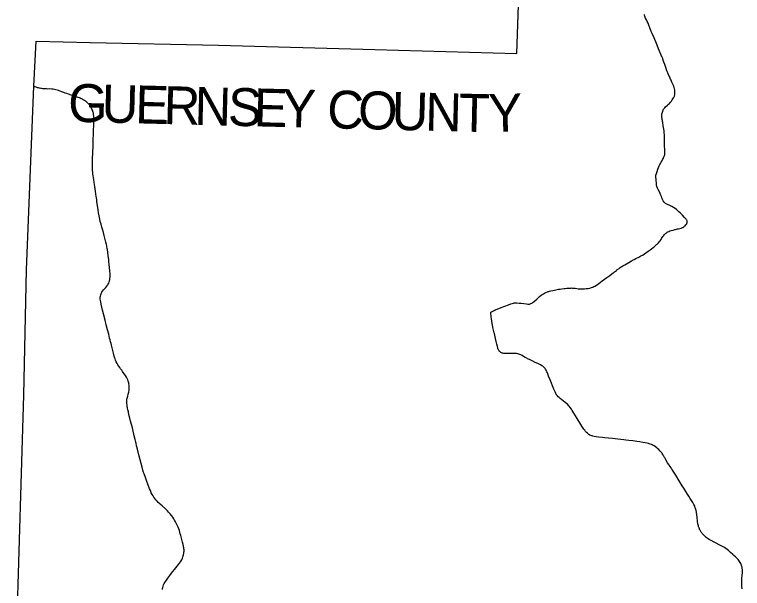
# Model space of a CAD drawing. Extents: x 1913970 to 2397567, y 78841 to 829347.
# Drawn here: x 2186978 to 2206160, y 770418 to 785537 of the extents above; entities that cross this region are included whole.
import ezdxf

# ---------------------------------------------------------------- set-up
doc = ezdxf.new("R2010")
doc.units = 0
for name, color, linetype in [('GM_X_County', 7, 'Continuous'), ('GM_X_County_Text', 7, 'Continuous'), ('GM_X_State_Location', 7, 'Continuous'), ('GM_X_State_Route', 7, 'Continuous')]:
    doc.layers.add(name, color=color, linetype=linetype)

msp = doc.modelspace()

# ---------------------------------------------------------------- linework, layer by layer
at = {"layer": 'GM_X_County'}
msp.add_lwpolyline([(2186978, 767293), (2187218, 775508), (2187296, 778812), (2187489, 783655), (2187543, 784833), (2188969, 784801), (2192356, 784732), (2196471, 784613), (2200213, 784515), (2200352, 788594), (2200607, 796487), (2200640, 798126), (2200752, 800346), (2200989, 806420)], dxfattribs=at)
at = {"layer": 'GM_X_State_Route'}
for points in [[(2204051, 784396), (2204046, 784409), (2204022, 784470), (2203977, 784572), (2203950, 784635), (2203911, 784733), (2203876, 784818), (2203831, 784920), (2203780, 785037), (2203757, 785095), (2203721, 785186), (2203693, 785262), (2203671, 785313), (2203652, 785354), (2203630, 785399), (2203606, 785445), (2203600, 785455), (2203596, 785464), (2203592, 785474), (2203588, 785483), (2203585, 785493), (2203584, 785499), (2203581, 785509), (2203579, 785522), (2203578, 785530), (2203577, 785542)], [(2204202, 783166), (2204210, 783173), (2204236, 783198), (2204262, 783228), (2204286, 783258), (2204310, 783288), (2204329, 783314), (2204343, 783339), (2204354, 783359), (2204361, 783374), (2204367, 783391), (2204370, 783405), (2204374, 783421), (2204378, 783447), (2204380, 783477), (2204379, 783514), (2204377, 783543), (2204370, 783579), (2204361, 783615), (2204348, 783652), (2204334, 783690), (2204303, 783760), (2204283, 783807), (2204268, 783835), (2204243, 783889), (2204214, 783953), (2204193, 784000), (2204171, 784058), (2204149, 784116), (2204115, 784220), (2204091, 784285), (2204073, 784338), (2204051, 784396)], [(2189061, 782905), (2189054, 782939), (2189050, 782955), (2189042, 782982), (2189037, 782998), (2189031, 783015), (2189017, 783048), (2188998, 783090), (2188988, 783108), (2188976, 783127), (2188962, 783146), (2188943, 783168), (2188925, 783187), (2188913, 783199), (2188901, 783210), (2188888, 783223), (2188864, 783243), (2188844, 783258), (2188825, 783270), (2188805, 783283), (2188786, 783295), (2188766, 783305), (2188750, 783314), (2188737, 783320), (2188703, 783334), (2188689, 783339), (2188652, 783352), (2188602, 783370), (2188553, 783386), (2188510, 783402), (2188467, 783417), (2188402, 783439), (2188358, 783454), (2188310, 783470), (2188272, 783484), (2188253, 783491), (2188238, 783496), (2188227, 783500), (2188180, 783517), (2188153, 783528), (2188132, 783537), (2188100, 783548), (2188064, 783558), (2188029, 783567), (2187992, 783573), (2187962, 783576), (2187911, 783577), (2187856, 783576), (2187823, 783577), (2187797, 783578), (2187757, 783580), (2187723, 783584), (2187695, 783587), (2187666, 783592), (2187636, 783599), (2187610, 783604), (2187583, 783611), (2187548, 783622), (2187525, 783629), (2187506, 783637), (2187490, 783652)], [(2204041, 782801), (2204038, 782821), (2204035, 782856), (2204035, 782878), (2204038, 782911), (2204044, 782942), (2204050, 782968), (2204060, 782995), (2204072, 783021), (2204083, 783041), (2204097, 783062), (2204114, 783084), (2204131, 783103), (2204185, 783152), (2204202, 783166)], [(2189142, 780669), (2189137, 780702), (2189122, 780807), (2189111, 780881), (2189101, 780945), (2189092, 781011), (2189077, 781110), (2189066, 781180), (2189056, 781248), (2189052, 781283), (2189044, 781344), (2189042, 781372), (2189036, 781434), (2189031, 781516), (2189030, 781607), (2189031, 781691), (2189035, 781772), (2189038, 781871), (2189042, 781956), (2189045, 782014), (2189048, 782066), (2189050, 782117), (2189051, 782166), (2189052, 782211), (2189053, 782285), (2189055, 782354), (2189057, 782429), (2189059, 782477), (2189060, 782522), (2189063, 782587), (2189064, 782617), (2189069, 782745), (2189070, 782811), (2189068, 782847), (2189067, 782860), (2189061, 782905)], [(2204102, 782202), (2204104, 782273), (2204103, 782347), (2204102, 782380), (2204101, 782413), (2204098, 782446), (2204095, 782472), (2204082, 782560), (2204075, 782602), (2204070, 782634), (2204064, 782667), (2204059, 782696), (2204054, 782721), (2204049, 782747), (2204045, 782773), (2204042, 782789), (2204041, 782801)], [(2206153, 770405), (2206146, 770471), (2206142, 770518), (2206141, 770561), (2206140, 770616), (2206143, 770673), (2206153, 770773), (2206158, 770822), (2206159, 770859), (2206160, 770894), (2206159, 770910), (2206154, 770955), (2206150, 770977), (2206146, 770994), (2206139, 771019), (2206134, 771032), (2206128, 771047), (2206116, 771075), (2206103, 771100), (2206082, 771131), (2206065, 771156), (2206044, 771181), (2206013, 771214), (2205976, 771250), (2205935, 771288), (2205907, 771312), (2205847, 771365), (2205788, 771416), (2205755, 771442), (2205719, 771470), (2205686, 771493), (2205650, 771514), (2205615, 771533), (2205549, 771568), (2205471, 771608), (2205411, 771640), (2205336, 771678), (2205290, 771703), (2205259, 771723), (2205229, 771743), (2205203, 771763), (2205163, 771800), (2205138, 771823), (2205113, 771851), (2205099, 771868), (2205088, 771882), (2205073, 771903), (2205063, 771918), (2205043, 771952), (2205032, 771974), (2205024, 771991), (2205015, 772011), (2205010, 772027), (2205006, 772038), (2205001, 772056), (2204998, 772070), (2204987, 772121), (2204976, 772179), (2204973, 772200), (2204963, 772284), (2204954, 772370), (2204949, 772409), (2204945, 772432), (2204938, 772468), (2204930, 772499), (2204917, 772543), (2204902, 772584), (2204882, 772627), (2204852, 772683), (2204820, 772737), (2204786, 772788), (2204749, 772846), (2204713, 772903), (2204670, 772969), (2204615, 773058), (2204573, 773124), (2204494, 773252), (2204401, 773400), (2204333, 773509), (2204306, 773550), (2204292, 773572), (2204278, 773595), (2204232, 773663), (2204216, 773687), (2204189, 773729), (2204141, 773805), (2204119, 773848), (2204105, 773872), (2204088, 773903), (2204075, 773924), (2204062, 773945), (2204045, 773970), (2204032, 773988), (2204012, 774013), (2203987, 774044), (2203959, 774075), (2203934, 774100), (2203903, 774126), (2203872, 774149), (2203837, 774171), (2203808, 774186), (2203779, 774200), (2203764, 774207), (2203732, 774219), (2203700, 774230), (2203685, 774235), (2203648, 774245), (2203596, 774256), (2203537, 774267), (2203453, 774280), (2203375, 774290), (2203330, 774295), (2203267, 774303), (2203167, 774315), (2203088, 774324), (2203036, 774330), (2202876, 774351), (2202733, 774368), (2202630, 774380), (2202537, 774390), (2202473, 774396), (2202368, 774407), (2202306, 774415), (2202251, 774424), (2202219, 774431), (2202197, 774437), (2202188, 774440), (2202168, 774447), (2202160, 774450), (2202142, 774459), (2202134, 774463), (2202113, 774475), (2202095, 774489), (2202075, 774506), (2202049, 774530), (2202027, 774555), (2202002, 774586), (2201983, 774613), (2201930, 774696), (2201878, 774780), (2201806, 774897), (2201760, 774969), (2201693, 775078), (2201673, 775108), (2201653, 775138), (2201621, 775183), (2201593, 775219), (2201574, 775242), (2201554, 775262), (2201525, 775288), (2201488, 775318), (2201401, 775384), (2201356, 775421), (2201327, 775446), (2201304, 775470), (2201284, 775492), (2201271, 775510), (2201267, 775516), (2201262, 775523), (2201251, 775540), (2201244, 775551), (2201231, 775576), (2201212, 775616), (2201192, 775667), (2201093, 775913), (2201053, 776014), (2201020, 776096), (2201006, 776129), (2200999, 776144), (2200987, 776167), (2200973, 776191), (2200960, 776210), (2200952, 776219), (2200935, 776240), (2200915, 776258), (2200897, 776272), (2200875, 776286), (2200842, 776305), (2200765, 776342), (2200694, 776375), (2200614, 776413), (2200546, 776446), (2200499, 776470), (2200479, 776481), (2200436, 776505), (2200388, 776533), (2200351, 776555), (2200320, 776571), (2200296, 776581), (2200269, 776591), (2200237, 776600), (2200205, 776606), (2200174, 776610), (2200137, 776611), (2200066, 776610), (2200003, 776607), (2199946, 776606), (2199911, 776606), (2199869, 776611), (2199845, 776616), (2199829, 776620), (2199807, 776629), (2199791, 776637), (2199782, 776643), (2199773, 776650), (2199763, 776658), (2199752, 776670), (2199745, 776678), (2199738, 776690), (2199729, 776705), (2199722, 776722), (2199717, 776735), (2199711, 776756), (2199701, 776791), (2199689, 776850), (2199673, 776920), (2199654, 777000), (2199633, 777087), (2199622, 777131), (2199617, 777153), (2199600, 777225), (2199586, 777289), (2199583, 777308), (2199566, 777402), (2199545, 777525), (2199538, 777578), (2199534, 777607), (2199531, 777642), (2199529, 777665), (2199527, 777700), (2199583, 777725), (2199603, 777735), (2199626, 777746), (2199641, 777752), (2199651, 777756), (2199672, 777763), (2199696, 777774), (2199802, 777816), (2199894, 777852), (2199997, 777894), (2200053, 777916), (2200090, 777928), (2200126, 777937), (2200148, 777941), (2200172, 777944), (2200211, 777944), (2200274, 777938), (2200332, 777931), (2200468, 777912), (2200501, 777909), (2200523, 777909), (2200546, 777911), (2200564, 777914), (2200586, 777921), (2200606, 777930), (2200625, 777941), (2200646, 777957), (2200684, 777988), (2200742, 778041), (2200751, 778050), (2200773, 778070), (2200792, 778088), (2200815, 778107), (2200858, 778143), (2200885, 778162), (2200913, 778179), (2200945, 778197), (2200975, 778211), (2201020, 778231), (2201039, 778238), (2201057, 778244), (2201073, 778249), (2201114, 778259), (2201159, 778269), (2201208, 778279), (2201275, 778293), (2201315, 778299), (2201356, 778306), (2201401, 778313), (2201463, 778320), (2201489, 778323), (2201528, 778327), (2201544, 778329), (2201570, 778330), (2201596, 778331), (2201635, 778333), (2201655, 778334), (2201685, 778333), (2201707, 778331), (2201724, 778329), (2201753, 778325), (2201792, 778321), (2201834, 778315), (2201876, 778311), (2201912, 778308), (2201954, 778308), (2202000, 778311), (2202045, 778316), (2202097, 778324), (2202142, 778333), (2202182, 778344), (2202219, 778358), (2202245, 778371), (2202270, 778385), (2202311, 778412), (2202373, 778455), (2202466, 778523), (2202527, 778567), (2202583, 778606), (2202612, 778628), (2202665, 778666), (2202718, 778705), (2202752, 778731), (2202759, 778737), (2202790, 778762), (2202837, 778798), (2202852, 778810), (2202907, 778851), (2202934, 778870), (2202962, 778888), (2203009, 778917), (2203063, 778948), (2203165, 779008), (2203235, 779049), (2203261, 779063), (2203305, 779086), (2203351, 779110), (2203427, 779148), (2203482, 779177), (2203522, 779200), (2203566, 779228), (2203577, 779235), (2203615, 779260), (2203644, 779281), (2203673, 779303), (2203699, 779323), (2203726, 779342), (2203762, 779369), (2203807, 779403), (2203830, 779420), (2203856, 779440), (2203899, 779476), (2203913, 779489), (2203945, 779522), (2203966, 779547), (2203989, 779578), (2204016, 779615), (2204028, 779634), (2204031, 779640), (2204065, 779689), (2204085, 779715), (2204106, 779741), (2204129, 779765), (2204146, 779780), (2204172, 779801), (2204192, 779812), (2204216, 779824), (2204250, 779838), (2204279, 779847), (2204333, 779861), (2204378, 779872), (2204397, 779876), (2204451, 779889), (2204454, 779889), (2204479, 779896), (2204508, 779903), (2204549, 779913), (2204579, 779924), (2204594, 779931), (2204616, 779943), (2204636, 779959), (2204653, 779974), (2204670, 779994), (2204681, 780009), (2204690, 780023), (2204697, 780037), (2204703, 780052), (2204705, 780066), (2204706, 780075), (2204706, 780085), (2204705, 780090), (2204703, 780098), (2204699, 780107), (2204693, 780118), (2204686, 780129), (2204673, 780148), (2204658, 780165), (2204632, 780194), (2204581, 780249), (2204517, 780313), (2204487, 780343), (2204452, 780376), (2204420, 780404), (2204387, 780430), (2204345, 780455), (2204302, 780478), (2204232, 780512), (2204199, 780528), (2204170, 780542), (2204135, 780563), (2204127, 780568), (2204097, 780595), (2204073, 780626), (2204055, 780665), (2204044, 780692), (2204037, 780710), (2204025, 780744), (2204011, 780777), (2204002, 780798), (2203988, 780827), (2203980, 780845), (2203942, 780924), (2203921, 780967), (2203908, 781005), (2203897, 781053), (2203891, 781102), (2203887, 781154), (2203883, 781199), (2203880, 781248), (2203878, 781281), (2203880, 781310), (2203891, 781352), (2203909, 781405), (2203932, 781465), (2203950, 781510), (2203967, 781550), (2203985, 781587), (2204027, 781664), (2204062, 781724), (2204079, 781758), (2204083, 781766), (2204099, 781805), (2204104, 781824), (2204111, 781846), (2204115, 781872), (2204117, 781897), (2204118, 781933), (2204114, 781999), (2204110, 782054), (2204104, 782161), (2204102, 782202)], [(2191439, 771476), (2191438, 771485), (2191433, 771515), (2191430, 771534), (2191420, 771576), (2191407, 771634), (2191360, 771809), (2191345, 771861), (2191334, 771902), (2191320, 771946), (2191303, 771992), (2191286, 772032), (2191262, 772086), (2191243, 772123), (2191218, 772174), (2191192, 772219), (2191173, 772250), (2191145, 772292), (2191119, 772329), (2191111, 772339), (2191078, 772381), (2191038, 772429), (2191008, 772463), (2190985, 772487), (2190953, 772519), (2190866, 772596), (2190824, 772632), (2190803, 772651), (2190766, 772686), (2190735, 772719), (2190703, 772755), (2190678, 772786), (2190650, 772823), (2190626, 772860), (2190608, 772891), (2190582, 772941), (2190556, 773000), (2190537, 773046), (2190519, 773092), (2190499, 773143), (2190453, 773266), (2190427, 773338), (2190392, 773434), (2190380, 773470), (2190360, 773531), (2190337, 773613), (2190310, 773711), (2190261, 773902), (2190215, 774084), (2190201, 774147), (2190193, 774176), (2190178, 774246), (2190171, 774275), (2190156, 774341), (2190134, 774440), (2190123, 774484), (2190103, 774564), (2190083, 774647), (2190066, 774710), (2190037, 774828), (2190018, 774902), (2190001, 774969), (2189982, 775050), (2189976, 775074), (2189965, 775128), (2189955, 775172), (2189949, 775202), (2189941, 775249), (2189934, 775298), (2189933, 775328), (2189935, 775354), (2189940, 775389), (2189948, 775433), (2189960, 775487), (2189971, 775532), (2189985, 775592), (2189996, 775643), (2189998, 775676), (2190000, 775703), (2190000, 775738), (2189998, 775773), (2189992, 775805), (2189985, 775838), (2189975, 775875), (2189961, 775911), (2189945, 775948), (2189925, 775986), (2189899, 776029), (2189868, 776075), (2189825, 776137), (2189803, 776165), (2189773, 776204), (2189748, 776238), (2189724, 776273), (2189701, 776309), (2189678, 776345), (2189659, 776384), (2189639, 776429), (2189625, 776471), (2189619, 776487), (2189606, 776536), (2189585, 776615), (2189559, 776726), (2189533, 776825), (2189521, 776871), (2189509, 776915), (2189496, 776964), (2189483, 777013), (2189458, 777115), (2189427, 777234), (2189394, 777364), (2189365, 777484), (2189322, 777651), (2189299, 777745), (2189260, 777910), (2189248, 777969), (2189241, 778005), (2189237, 778035), (2189235, 778059), (2189235, 778070), (2189236, 778093), (2189240, 778122), (2189249, 778153), (2189257, 778177), (2189269, 778204), (2189281, 778227), (2189298, 778253), (2189319, 778281), (2189338, 778303), (2189381, 778348), (2189413, 778385), (2189434, 778415), (2189445, 778435), (2189460, 778465), (2189472, 778496), (2189478, 778517), (2189486, 778553), (2189491, 778586), (2189494, 778625), (2189495, 778665), (2189493, 778705), (2189487, 778780), (2189478, 778871), (2189470, 778955), (2189464, 779020), (2189458, 779080), (2189447, 779180), (2189435, 779269), (2189424, 779349), (2189420, 779377), (2189412, 779424), (2189408, 779446), (2189400, 779478), (2189384, 779545), (2189340, 779716), (2189319, 779798), (2189296, 779880), (2189280, 779936), (2189257, 780019), (2189238, 780089), (2189224, 780150), (2189206, 780237), (2189193, 780318), (2189180, 780399), (2189150, 780607), (2189142, 780669)], [(2190875, 770387), (2190879, 770420), (2190884, 770445), (2190895, 770480), (2190907, 770514), (2190924, 770549), (2190940, 770577), (2190961, 770610), (2190996, 770659), (2191018, 770690), (2191045, 770727), (2191070, 770759), (2191115, 770819), (2191151, 770864), (2191191, 770914), (2191227, 770960), (2191294, 771046), (2191348, 771120), (2191367, 771148), (2191382, 771174), (2191402, 771215), (2191415, 771247), (2191425, 771275), (2191433, 771307), (2191440, 771347), (2191442, 771377), (2191444, 771404), (2191443, 771435), (2191440, 771466), (2191439, 771476)]]:
    msp.add_lwpolyline(points, dxfattribs=at)

# ---------------------------------------------------------------- texts
at = {"layer": 'GM_X_County_Text'}
for s, rotation, p in [('G', 358.5416, (2188380, 782718)), ('U', 358.5422, (2189264, 782696)), ('E', 358.5419, (2190148, 782673)), ('R', 358.5416, (2190896, 782654)), ('N', 358.5427, (2191710, 782633)), ('S', 358.5408, (2192594, 782611)), ('E', 358.5423, (2193271, 782594)), ('Y', 358.5417, (2194019, 782575)), ('C', 358.5413, (2195207, 782544)), ('O', 358.5414, (2196021, 782524)), ('U', 358.5421, (2196905, 782501)), ('N', 358.5446, (2197789, 782479)), ('T', 358.7696, (2198677, 782456)), ('Y', 1.3227, (2199474, 782440))]:
    msp.add_text(s, height=1000, rotation=rotation, dxfattribs=at).set_placement(p)
at = {"layer": 'GM_X_State_Location'}
for s, p in [('s', (2189256, 778047)), ('r', (2189256, 778047)), ('s', (2201941, 774571)), ('r', (2201941, 774571))]:
    msp.add_text(s, height=1, dxfattribs=at).set_placement(p)
for s, p in [('662', (2188903, 777974)), ('658', (2201588, 774498))]:
    msp.add_text(s, height=1, rotation=0, dxfattribs=at).set_placement(p)

doc.saveas('drawing.dxf')
